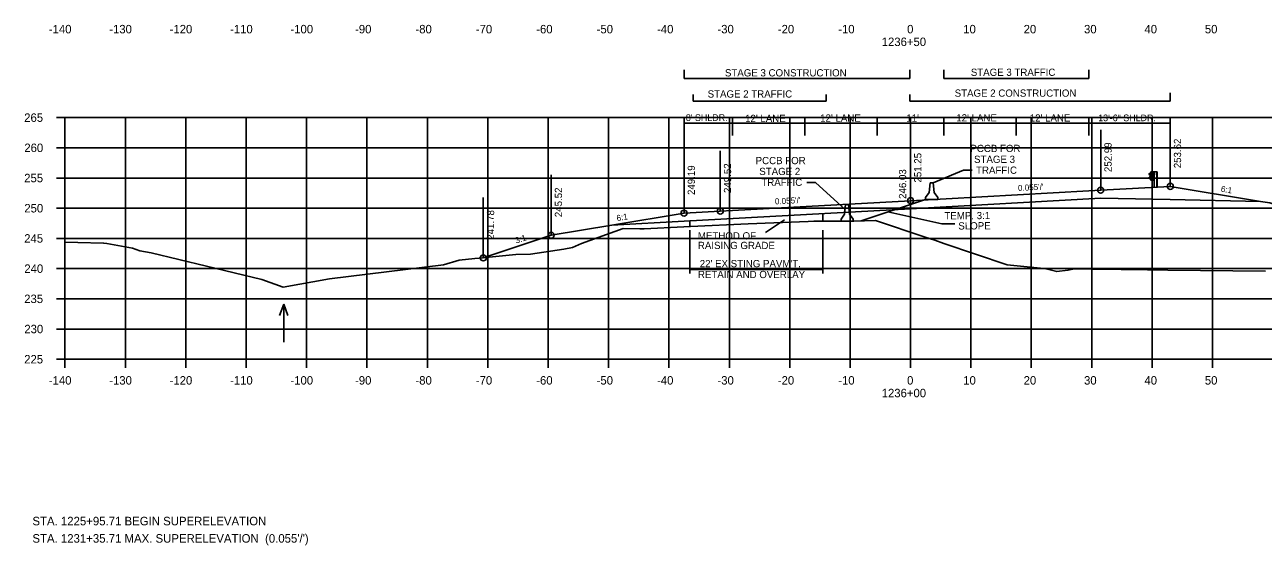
# Model space of a CAD drawing. Extents: x 1342547 to 1344156, y -1532351 to -1517216.
# Drawn here: x 1342556.2 to 1342761.3, y -1529378.4 to -1529292.2 of the extents above; entities that cross this region are included whole.
import ezdxf

# ---------------------------------------------------------------- set-up
doc = ezdxf.new("R2010")
doc.units = 0
for name, color, linetype in [('R_Alt Surface', 7, 'Continuous'), ('R_Axis', 7, 'Continuous'), ('R_Axis Annot', 7, 'Continuous'), ('R_Border Notes', 7, 'Continuous'), ('R_Draft', 7, 'Continuous'), ('R_Exist Surface', 7, 'Continuous'), ('R_Fin Surface', 7, 'Continuous'), ('R_Grid', 7, 'Continuous'), ('R_MOT', 7, 'Continuous'), ('R_No Plot', 7, 'Continuous'), ('R_Water', 7, 'Continuous'), ('R_Xsect Elev', 7, 'Continuous'), ('R_Xsect Slope', 7, 'Continuous')]:
    doc.layers.add(name, color=color, linetype=linetype)

msp = doc.modelspace()

# ---------------------------------------------------------------- linework, layer by layer
at = {"layer": 'R_Alt Surface'}
for points in [[(1342745.87, -1529321.15), (1342734.37, -1529320.92), (1342702.87, -1529322.65)], [(1342745.87, -1529321.15), (1342760.84, -1529321.45)], [(1342665.37, -1529324.71), (1342702.87, -1529322.65)], [(1342653.42, -1529325.37), (1342665.37, -1529324.71)], [(1342665.37, -1529324.71), (1342666.33, -1529324.66)]]:
    msp.add_lwpolyline(points, dxfattribs=at)
at = {"layer": 'R_Axis'}
for p, q in [((1342561.47, -1529307.57), (1342562.87, -1529307.57)), ((1342562.87, -1529347.57), (1342562.87, -1529307.57)), ((1342561.47, -1529312.57), (1342562.87, -1529312.57)), ((1342561.47, -1529317.57), (1342562.87, -1529317.57)), ((1342561.47, -1529322.57), (1342562.87, -1529322.57)), ((1342561.47, -1529327.57), (1342562.87, -1529327.57)), ((1342561.47, -1529332.57), (1342562.87, -1529332.57)), ((1342561.47, -1529337.57), (1342562.87, -1529337.57)), ((1342561.47, -1529342.57), (1342562.87, -1529342.57)), ((1342561.47, -1529347.57), (1342562.87, -1529347.57)), ((1342562.87, -1529347.57), (1342842.87, -1529347.57)), ((1342562.87, -1529348.97), (1342562.87, -1529347.57)), ((1342572.87, -1529348.97), (1342572.87, -1529347.57)), ((1342582.87, -1529348.97), (1342582.87, -1529347.57)), ((1342592.87, -1529348.97), (1342592.87, -1529347.57)), ((1342602.87, -1529348.97), (1342602.87, -1529347.57)), ((1342612.87, -1529348.97), (1342612.87, -1529347.57)), ((1342622.87, -1529348.97), (1342622.87, -1529347.57)), ((1342632.87, -1529348.97), (1342632.87, -1529347.57)), ((1342642.87, -1529348.97), (1342642.87, -1529347.57)), ((1342652.87, -1529348.97), (1342652.87, -1529347.57)), ((1342662.87, -1529348.97), (1342662.87, -1529347.57)), ((1342672.87, -1529348.97), (1342672.87, -1529347.57)), ((1342682.87, -1529348.97), (1342682.87, -1529347.57)), ((1342692.87, -1529348.97), (1342692.87, -1529347.57)), ((1342702.87, -1529348.97), (1342702.87, -1529347.57)), ((1342712.87, -1529348.97), (1342712.87, -1529347.57)), ((1342722.87, -1529348.97), (1342722.87, -1529347.57)), ((1342732.87, -1529348.97), (1342732.87, -1529347.57)), ((1342742.87, -1529348.97), (1342742.87, -1529347.57)), ((1342752.87, -1529348.97), (1342752.87, -1529347.57))]:
    msp.add_line(p, q, dxfattribs=at)
at = {"layer": 'R_Draft'}
for p, q in [((1342665.37, -1529301.08), (1342665.37, -1529299.65)), ((1342702.78, -1529301.08), (1342702.78, -1529299.65)), ((1342708.37, -1529301.08), (1342708.37, -1529299.65)), ((1342732.37, -1529301.08), (1342732.37, -1529299.65)), ((1342665.37, -1529301.08), (1342702.78, -1529301.08)), ((1342708.37, -1529301.08), (1342732.37, -1529301.08)), ((1342666.88, -1529304.87), (1342666.88, -1529303.73)), ((1342688.88, -1529304.87), (1342688.88, -1529303.73)), ((1342702.78, -1529304.87), (1342702.78, -1529303.73)), ((1342745.87, -1529304.87), (1342745.87, -1529303.44)), ((1342666.88, -1529304.87), (1342688.88, -1529304.87)), ((1342702.78, -1529304.87), (1342745.87, -1529304.87)), ((1342742.39, -1529316.85), (1342742.52, -1529316.75)), ((1342742.56, -1529317.1), (1342742.39, -1529317)), ((1342742.51, -1529317.7), (1342742.39, -1529317.59)), ((1342742.4, -1529316.87), (1342742.53, -1529316.76)), ((1342742.58, -1529317.08), (1342742.4, -1529316.97)), ((1342742.53, -1529317.68), (1342742.4, -1529317.57)), ((1342742.41, -1529317.43), (1342742.57, -1529317.33)), ((1342742.43, -1529317.45), (1342742.58, -1529317.35)), ((1342742.63, -1529317.76), (1342742.51, -1529317.7)), ((1342742.52, -1529316.75), (1342742.63, -1529316.69)), ((1342742.53, -1529316.76), (1342742.62, -1529316.71)), ((1342742.63, -1529317.74), (1342742.53, -1529317.68)), ((1342742.6, -1529317.28), (1342742.6, -1529317.15)), ((1342742.62, -1529317.28), (1342742.62, -1529317.15)), ((1342742.66, -1529317.9), (1342742.66, -1529316.54)), ((1342742.67, -1529317.28), (1342742.67, -1529317.16)), ((1342742.67, -1529317.16), (1342742.72, -1529317.16)), ((1342742.67, -1529317.19), (1342742.72, -1529317.19)), ((1342742.67, -1529317.25), (1342742.72, -1529317.25)), ((1342742.67, -1529317.25), (1342742.72, -1529317.25)), ((1342742.67, -1529317.28), (1342742.72, -1529317.28)), ((1342742.73, -1529317.27), (1342742.73, -1529317.17)), ((1342743.15, -1529316.84), (1342743.1, -1529316.84)), ((1342743.1, -1529316.84), (1342743.1, -1529316.96)), ((1342743.15, -1529316.96), (1342743.1, -1529316.96)), ((1342743.1, -1529317.65), (1342743.1, -1529317.52)), ((1342743.1, -1529317.52), (1342743.15, -1529317.52)), ((1342743.1, -1529317.65), (1342743.15, -1529317.65)), ((1342743.11, -1529316.9), (1342743.16, -1529316.9)), ((1342743.11, -1529317.59), (1342743.16, -1529317.59)), ((1342743.16, -1529316.53), (1342743.17, -1529316.53)), ((1342743.16, -1529316.53), (1342743.23, -1529316.53)), ((1342743.16, -1529317.9), (1342743.2, -1529317.9)), ((1342743.19, -1529319.05), (1342743.19, -1529316.53)), ((1342743.23, -1529316.96), (1342743.23, -1529316.83)), ((1342743.23, -1529316.83), (1342743.28, -1529316.83)), ((1342743.23, -1529316.86), (1342743.28, -1529316.86)), ((1342743.23, -1529316.93), (1342743.27, -1529316.93)), ((1342743.23, -1529316.93), (1342743.28, -1529316.93)), ((1342743.23, -1529316.96), (1342743.28, -1529316.96)), ((1342743.24, -1529317.65), (1342743.24, -1529317.52)), ((1342743.24, -1529317.52), (1342743.29, -1529317.52)), ((1342743.24, -1529317.55), (1342743.29, -1529317.55)), ((1342743.24, -1529317.62), (1342743.28, -1529317.62)), ((1342743.24, -1529317.62), (1342743.29, -1529317.62)), ((1342743.24, -1529317.65), (1342743.29, -1529317.65)), ((1342743.29, -1529316.94), (1342743.29, -1529316.85)), ((1342743.3, -1529317.63), (1342743.3, -1529317.54)), ((1342743.66, -1529316.53), (1342743.66, -1529319.05)), ((1342743.69, -1529316.53), (1342743.69, -1529319.05)), ((1342688.33, -1529323.45), (1342688.33, -1529324.7)), ((1342666.33, -1529324.66), (1342666.33, -1529325.61)), ((1342666.33, -1529326.18), (1342666.33, -1529333.37)), ((1342688.33, -1529326.18), (1342688.33, -1529333.37)), ((1342666.33, -1529332.7), (1342688.33, -1529332.7))]:
    msp.add_line(p, q, dxfattribs=at)
for points in [[(1342711.62, -1529316.29), (1342706.61, -1529318.37)], [(1342713.06, -1529316.29), (1342711.62, -1529316.29)], [(1342743.69, -1529316.53), (1342743.23, -1529316.53), (1342743.23, -1529319.05)], [(1342685.71, -1529318.31), (1342687.15, -1529318.31)], [(1342687.15, -1529318.31), (1342692.04, -1529322.76)]]:
    msp.add_lwpolyline(points, dxfattribs=at)
for points in [[(1342742.64, -1529316.53), (1342742.64, -1529317.9), (1342743.16, -1529317.9), (1342743.16, -1529316.53)], [(1342742.68, -1529317.14), (1342742.68, -1529317.3), (1342742.67, -1529317.3), (1342742.67, -1529317.14)], [(1342742.73, -1529317.19), (1342742.73, -1529317.25), (1342742.76, -1529317.25), (1342742.76, -1529317.19)], [(1342743.11, -1529316.84), (1342743.11, -1529316.96), (1342743.16, -1529316.96), (1342743.16, -1529316.84)], [(1342743.11, -1529317.52), (1342743.11, -1529317.65), (1342743.16, -1529317.65), (1342743.16, -1529317.52)], [(1342743.23, -1529316.81), (1342743.23, -1529316.98), (1342743.22, -1529316.98), (1342743.22, -1529316.81)], [(1342743.24, -1529317.5), (1342743.24, -1529317.67), (1342743.23, -1529317.67), (1342743.23, -1529317.5)], [(1342743.29, -1529316.87), (1342743.29, -1529316.93), (1342743.31, -1529316.93), (1342743.31, -1529316.87)], [(1342743.3, -1529317.55), (1342743.3, -1529317.62), (1342743.32, -1529317.62), (1342743.32, -1529317.55)]]:
    msp.add_lwpolyline(points, close=True, dxfattribs=at)
for centre, radius, start, end in [((1342742.43, -1529316.92), 0.0856, 122.0217, 240.7501), ((1342742.47, -1529317.52), 0.109, 120.88, 214.7816), ((1342742.43, -1529316.92), 0.062, 122.0217, 240.7501), ((1342742.47, -1529317.52), 0.0854, 120.88, 214.7816), ((1342742.54, -1529317.16), 0.0622, 4.9556, 61.894), ((1342742.6, -1529317.22), 0.0453, 93.9303, 257.0446), ((1342742.55, -1529317.29), 0.0462, 293.1464, 8.2196), ((1342742.54, -1529317.16), 0.0865, 4.9556, 61.894), ((1342742.55, -1529317.29), 0.0703, 293.1464, 8.2196), ((1342742.71, -1529317.17), 0.022, 317.7756, 45.4255), ((1342742.64, -1529317.22), 0.0922, 339.7423, 20.2577), ((1342742.7, -1529317.27), 0.025, 323.3766, 39.0666), ((1342743.26, -1529316.85), 0.022, 317.7756, 45.4255), ((1342743.19, -1529316.9), 0.0922, 339.7423, 20.2577), ((1342743.26, -1529316.94), 0.025, 323.3766, 39.0666), ((1342743.27, -1529317.54), 0.022, 317.7756, 45.4255), ((1342743.2, -1529317.59), 0.0922, 339.7423, 20.2577), ((1342743.27, -1529317.63), 0.025, 323.3766, 39.0666)]:
    msp.add_arc(centre, radius, start, end, dxfattribs=at)
at = {"layer": 'R_Exist Surface'}
msp.add_lwpolyline([(1342562.87, -1529328.18), (1342562.91, -1529328.18), (1342565, -1529328.23), (1342569.26, -1529328.34), (1342569.8, -1529328.43), (1342574.03, -1529329.18), (1342575.29, -1529329.64), (1342577.13, -1529329.97), (1342595.44, -1529334.39), (1342599.01, -1529335.62), (1342606.65, -1529334.28), (1342625.55, -1529331.93), (1342628.14, -1529331.18), (1342630.72, -1529330.88), (1342631.46, -1529330.86), (1342637.54, -1529330.24), (1342639.92, -1529330.18), (1342645.45, -1529329.37), (1342646.88, -1529329.07), (1342648.41, -1529328.43), (1342655.3, -1529325.91), (1342658.05, -1529325.98), (1342658.23, -1529325.99), (1342658.78, -1529325.96), (1342665.36, -1529325.67), (1342666.44, -1529325.61), (1342675.98, -1529325.13), (1342685.94, -1529324.75), (1342686.88, -1529324.72), (1342692.73, -1529324.72), (1342693.22, -1529324.72), (1342693.49, -1529324.7), (1342697.05, -1529324.61), (1342705.28, -1529327.34), (1342706.9, -1529327.86), (1342708.36, -1529328.39), (1342718.85, -1529331.94), (1342724.95, -1529332.54), (1342725.17, -1529332.57), (1342725.35, -1529332.61), (1342727.09, -1529333.07), (1342728.92, -1529332.85), (1342730.04, -1529332.63), (1342732.8, -1529332.67), (1342737.73, -1529332.7), (1342742.08, -1529332.79), (1342745.46, -1529332.83), (1342761.65, -1529333.01)], dxfattribs=at)
at = {"layer": 'R_Fin Surface'}
msp.add_line((1342694.71, -1529324.67), (1342705.36, -1529321.12), dxfattribs=at)
msp.add_lwpolyline([(1342632.13, -1529330.79), (1342643.37, -1529327.05), (1342653.42, -1529325.37), (1342665.37, -1529323.38), (1342671.37, -1529323.05), (1342673.37, -1529322.94), (1342702.87, -1529321.32), (1342732.37, -1529319.69), (1342734.37, -1529319.58), (1342745.87, -1529318.95), (1342760.84, -1529321.45), (1342762.37, -1529321.7), (1342790.99, -1529331.24)], dxfattribs=at)
at = {"layer": 'R_Grid'}
for p, q in [((1342562.87, -1529307.57), (1342842.87, -1529307.57)), ((1342562.87, -1529347.57), (1342562.87, -1529307.57)), ((1342572.87, -1529347.57), (1342572.87, -1529307.57)), ((1342582.87, -1529347.57), (1342582.87, -1529307.57)), ((1342592.87, -1529347.57), (1342592.87, -1529307.57)), ((1342602.87, -1529347.57), (1342602.87, -1529307.57)), ((1342612.87, -1529347.57), (1342612.87, -1529307.57)), ((1342622.87, -1529347.57), (1342622.87, -1529307.57)), ((1342632.87, -1529347.57), (1342632.87, -1529307.57)), ((1342642.87, -1529347.57), (1342642.87, -1529307.57)), ((1342652.87, -1529347.57), (1342652.87, -1529307.57)), ((1342662.87, -1529347.57), (1342662.87, -1529307.57)), ((1342672.87, -1529347.57), (1342672.87, -1529307.57)), ((1342682.87, -1529347.57), (1342682.87, -1529307.57)), ((1342692.87, -1529347.57), (1342692.87, -1529307.57)), ((1342702.87, -1529347.57), (1342702.87, -1529307.57)), ((1342712.87, -1529347.57), (1342712.87, -1529307.57)), ((1342722.87, -1529347.57), (1342722.87, -1529307.57)), ((1342732.87, -1529347.57), (1342732.87, -1529307.57)), ((1342742.87, -1529347.57), (1342742.87, -1529307.57)), ((1342752.87, -1529347.57), (1342752.87, -1529307.57)), ((1342562.87, -1529312.57), (1342842.87, -1529312.57)), ((1342562.87, -1529317.57), (1342842.87, -1529317.57)), ((1342562.87, -1529322.57), (1342842.87, -1529322.57)), ((1342562.87, -1529327.57), (1342842.87, -1529327.57)), ((1342562.87, -1529332.57), (1342842.87, -1529332.57)), ((1342562.87, -1529337.57), (1342842.87, -1529337.57)), ((1342562.87, -1529342.57), (1342842.87, -1529342.57)), ((1342562.87, -1529347.57), (1342842.87, -1529347.57))]:
    msp.add_line(p, q, dxfattribs=at)
at = {"layer": 'R_MOT'}
for p, q in [((1342705.37, -1529320.79), (1342705.95, -1529319.95)), ((1342705.95, -1529319.95), (1342706.11, -1529318.37)), ((1342706.36, -1529318.37), (1342706.11, -1529318.37)), ((1342706.61, -1529318.37), (1342706.36, -1529318.37)), ((1342706.78, -1529319.95), (1342706.61, -1529318.37)), ((1342707.37, -1529320.79), (1342706.78, -1529319.95)), ((1342691.95, -1529323.55), (1342692.12, -1529321.97)), ((1342692.37, -1529321.97), (1342692.12, -1529321.97)), ((1342692.62, -1529321.97), (1342692.37, -1529321.97)), ((1342692.79, -1529323.55), (1342692.62, -1529321.97)), ((1342705.36, -1529321.12), (1342705.37, -1529320.79)), ((1342707.37, -1529321.12), (1342705.36, -1529321.12)), ((1342707.37, -1529321.12), (1342707.37, -1529320.79)), ((1342691.38, -1529324.39), (1342691.95, -1529323.55)), ((1342693.38, -1529324.39), (1342692.79, -1529323.55)), ((1342691.37, -1529324.72), (1342691.38, -1529324.39)), ((1342693.37, -1529324.72), (1342691.37, -1529324.72)), ((1342693.37, -1529324.72), (1342693.38, -1529324.39))]:
    msp.add_line(p, q, dxfattribs=at)
at = {"layer": 'R_No Plot'}
for centre in [(1342734.37, -1529319.58), (1342745.87, -1529318.95), (1342702.87, -1529321.32), (1342665.37, -1529323.38), (1342671.37, -1529323.05), (1342643.37, -1529327.05), (1342632.13, -1529330.79)]:
    msp.add_circle(centre, 0.5, dxfattribs=at)
at = {"layer": 'R_Water'}
for p, q in [((1342599.09, -1529338.43), (1342598.39, -1529340.35)), ((1342599.09, -1529344.72), (1342599.09, -1529338.43)), ((1342599.09, -1529338.43), (1342599.79, -1529340.35))]:
    msp.add_line(p, q, dxfattribs=at)
at = {"layer": 'R_Xsect Elev'}
for p, q in [((1342665.37, -1529322.19), (1342665.37, -1529307.65)), ((1342673.37, -1529310.51), (1342673.37, -1529307.65)), ((1342685.37, -1529310.51), (1342685.37, -1529307.65)), ((1342697.37, -1529310.51), (1342697.37, -1529307.65)), ((1342708.37, -1529310.51), (1342708.37, -1529307.65)), ((1342720.37, -1529310.51), (1342720.37, -1529307.65)), ((1342732.37, -1529310.51), (1342732.37, -1529307.65)), ((1342745.87, -1529318.95), (1342745.87, -1529307.65)), ((1342745.87, -1529308.51), (1342665.37, -1529308.51)), ((1342734.37, -1529319.58), (1342734.37, -1529309.58)), ((1342745.87, -1529318.95), (1342745.87, -1529308.95)), ((1342745.87, -1529318.95), (1342745.87, -1529308.95)), ((1342702.87, -1529321.32), (1342702.87, -1529311.32)), ((1342665.37, -1529323.38), (1342665.37, -1529313.38)), ((1342665.37, -1529323.38), (1342665.37, -1529313.38)), ((1342671.37, -1529323.05), (1342671.37, -1529313.05)), ((1342643.37, -1529327.05), (1342643.37, -1529317.05)), ((1342702.87, -1529326.54), (1342702.87, -1529316.54)), ((1342632.13, -1529330.79), (1342632.13, -1529320.79)), ((1342699.09, -1529323.18), (1342708.04, -1529325.15)), ((1342681.99, -1529324.49), (1342678.84, -1529326.6)), ((1342708.04, -1529325.15), (1342710.18, -1529325.15))]:
    msp.add_line(p, q, dxfattribs=at)

# ---------------------------------------------------------------- texts
at = {"layer": 'R_Axis Annot'}
for s, p in [('-140', (1342560.2, -1529293.62)), ('-130', (1342570.2, -1529293.62)), ('-120', (1342580.2, -1529293.62)), ('-110', (1342590.2, -1529293.62)), ('-100', (1342600.2, -1529293.62)), ('-90', (1342610.9, -1529293.62)), ('-80', (1342620.9, -1529293.62)), ('-70', (1342630.9, -1529293.62)), ('-60', (1342640.9, -1529293.62)), ('-50', (1342650.9, -1529293.62)), ('-40', (1342660.9, -1529293.62)), ('-30', (1342670.9, -1529293.62)), ('-20', (1342680.9, -1529293.62)), ('-10', (1342690.9, -1529293.62)), ('0', (1342702.3, -1529293.62)), ('10', (1342711.6, -1529293.62)), ('20', (1342721.6, -1529293.62)), ('30', (1342731.6, -1529293.62)), ('40', (1342741.6, -1529293.62)), ('50', (1342751.6, -1529293.62)), ('1236+50', (1342698.1, -1529295.72)), ('265', (1342556.12, -1529308.27)), ('260', (1342556.14, -1529313.27)), ('255', (1342556.12, -1529318.27)), ('250', (1342556.14, -1529323.27)), ('245', (1342556.12, -1529328.27)), ('240', (1342556.14, -1529333.27)), ('235', (1342556.12, -1529338.27)), ('230', (1342556.14, -1529343.27)), ('225', (1342556.12, -1529348.27)), ('-140', (1342560.2, -1529351.77)), ('-130', (1342570.2, -1529351.77)), ('-120', (1342580.2, -1529351.77)), ('-110', (1342590.2, -1529351.77)), ('-100', (1342600.2, -1529351.77)), ('-90', (1342610.9, -1529351.77)), ('-80', (1342620.9, -1529351.77)), ('-70', (1342630.9, -1529351.77)), ('-60', (1342640.9, -1529351.77)), ('-50', (1342650.9, -1529351.77)), ('-40', (1342660.9, -1529351.77)), ('-30', (1342670.9, -1529351.77)), ('-20', (1342680.9, -1529351.77)), ('-10', (1342690.9, -1529351.77)), ('0', (1342702.3, -1529351.77)), ('10', (1342711.6, -1529351.77)), ('20', (1342721.6, -1529351.77)), ('30', (1342731.6, -1529351.77)), ('40', (1342741.6, -1529351.77)), ('50', (1342751.6, -1529351.77)), ('1236+00', (1342698.1, -1529353.87))]:
    msp.add_text(s, height=1.4, dxfattribs=at).set_placement(p)
at = {"layer": 'R_Border Notes'}
for s, p in [('STA. 1225+95.71 BEGIN SUPERELEVATION', (1342557.48, -1529375.07)), ("STA. 1231+35.71 MAX. SUPERELEVATION  (0.055'/')", (1342557.48, -1529377.94))]:
    msp.add_text(s, height=1.41, dxfattribs=at).set_placement(p)
at = {"layer": 'R_Draft'}
for s, p in [('STAGE 3 CONSTRUCTION', (1342672.14, -1529300.75)), ('STAGE 3 TRAFFIC', (1342712.85, -1529300.66)), ('STAGE 2 TRAFFIC', (1342669.28, -1529304.25)), ('STAGE 2 CONSTRUCTION', (1342710.18, -1529304.11)), ('PCCB FOR', (1342677.22, -1529315.28)), ('PCCB FOR', (1342712.78, -1529313.27)), ('STAGE 3', (1342713.39, -1529315.07)), ('STAGE 2', (1342677.83, -1529317.08)), ('TRAFFIC', (1342713.72, -1529316.87)), ('TRAFFIC', (1342678.17, -1529318.88)), ("22' EXISTING PAVM'T.", (1342667.97, -1529332.34)), ('RETAIN AND OVERLAY', (1342667.67, -1529334.14))]:
    msp.add_text(s, height=1.2, dxfattribs=at).set_placement(p)
at = {"layer": 'R_Xsect Elev'}
for s, height, p in [("8' SHLDR.", 1.1, (1342665.67, -1529308.12)), ("12' LANE", 1.2, (1342675.48, -1529308.3)), ("12' LANE", 1.2, (1342687.91, -1529308.24)), ("11'", 1.2, (1342702.18, -1529308.24)), ("12' LANE", 1.2, (1342710.44, -1529308.21)), ("12' LANE", 1.2, (1342722.61, -1529308.23)), ('13\'-6" SHLDR.', 1.1, (1342733.94, -1529308.16)), ('METHOD OF', 1.2, (1342667.66, -1529327.74)), ('RAISING GRADE', 1.2, (1342667.66, -1529329.33))]:
    msp.add_text(s, height=height, dxfattribs=at).set_placement(p)
for s, p in [('252.99', (1342736.17, -1529316.58)), ('253.62', (1342747.67, -1529315.95)), ('251.25', (1342704.67, -1529318.32)), ('249.19', (1342667.17, -1529320.38)), ('249.52', (1342673.17, -1529320.05)), ('246.03', (1342702.15, -1529321.02)), ('245.52', (1342645.17, -1529324.05)), ('241.78', (1342633.93, -1529327.79))]:
    msp.add_text(s, height=1.2, rotation=90, dxfattribs=at).set_placement(p)
at = {"layer": 'R_Xsect Slope'}
for s, height, rotation, p in [("0.055'/'", 1, 3.1481, (1342720.69, -1529319.73)), ('6:1', 1, 350.5377, (1342754.2, -1529319.83)), ("0.055'/'", 1, 3.1481, (1342680.44, -1529321.95)), ('6:1', 1, 9.4623, (1342654.28, -1529324.72)), ('TEMP. 3:1', 1.2, 0.3758, (1342708.48, -1529324.42)), ('SLOPE', 1.2, 0.3758, (1342710.79, -1529326.1)), ('3:1', 1, 18.4349, (1342637.59, -1529328.44))]:
    msp.add_text(s, height=height, rotation=rotation, dxfattribs=at).set_placement(p)

doc.saveas('drawing.dxf')
